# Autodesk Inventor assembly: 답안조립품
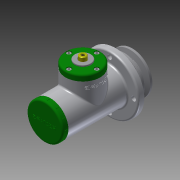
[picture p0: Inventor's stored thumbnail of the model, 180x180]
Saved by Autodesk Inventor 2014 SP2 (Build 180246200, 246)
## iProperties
Created: 2016-08
Part Number: 답안조립품
Document SubType Name: Assembly
Designer: 달림반
Author: 달림반
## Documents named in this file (24)
- C:\Users\달림반\Desktop\460807V1024\답안조립품.iam
- C:\Users\달림반\Desktop\460807V1024\본체.ipt
- C:\Users\달림반\Desktop\460807V1024\사이드 커버.ipt
- 사이드 커버.ipt
- C:\Users\달림반\Desktop\460807V1024\탑 커버.ipt
- 탑 커버.ipt
- C:\Users\달림반\Desktop\460807V1024\탑 부시.ipt
- C:\Users\달림반\Desktop\460807V1024\편심축.ipt
- C:\Users\달림반\Desktop\460807V1024\멈춤링 15 x 1.ipt
- C:\Users\달림반\Desktop\460807V1024\멈춤링 35x1.6.ipt
- C:\Users\달림반\Desktop\460807V1024\베어링 15 x 35 x 11.ipt
- C:\Users\달림반\Desktop\460807V1024\링크.ipt
- C:\Users\달림반\Desktop\460807V1024\슬라이더.ipt
- C:\Users\달림반\Desktop\460807V1024\클래스터 핀 6 x 24.ipt
- C:\Users\달림반\Desktop\460807V1024\분할핀 1.6 x 12.ipt
- C:\Users\달림반\Desktop\460807V1024\부시1.ipt
- C:\Users\달림반\Desktop\460807V1024\너트 M10.ipt
- C:\Users\달림반\Desktop\460807V1024\오일 실 15 25 7.ipt
- C:\Users\달림반\Desktop\460807V1024\와셔 10x21.ipt
- C:\Users\달림반\Desktop\460807V1024\V-벨트풀리.ipt
- C:\Users\달림반\Desktop\460807V1024\와셔 4x16.ipt
- C:\Users\달림반\Desktop\460807V1024\키 4 x 4 x 18.ipt
- C:\Users\달림반\Desktop\460807V1024\볼트 M4 x 10.ipt
- C:\Users\달림반\Desktop\460807V1024\볼트 M4 x 12.ipt
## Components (6 placed, 3 different names)
1. V-벨트풀리:1
2. ISO 4017 M4 x 10:1
3. ISO 4762 M4 x 12:1
4. ISO 4762 M4 x 12:2
5. ISO 4762 M4 x 12:3
6. ISO 4762 M4 x 12:4
